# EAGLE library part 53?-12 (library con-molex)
CONNECTOR wire to board 1.25 mm (.049 inch) pitch header
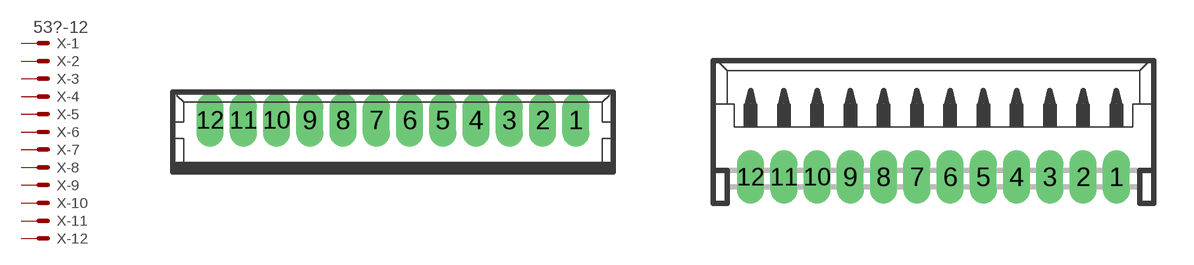
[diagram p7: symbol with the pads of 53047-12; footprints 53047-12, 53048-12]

Designator prefix X; gates -1=MV -2=M -3=M -4=M -5=M -6=M -7=M -8=M -9=M -10=M -11=M -12=M

## 53047-12 (MF: WALDOM/MOLEX; MPN: 53047-1210; OC_FARNELL: 9732896; OC_NEWARK: 18M8169)  [53047-12]
1  -1:S  pas
2  -2:S  pas
3  -3:S  pas
4  -4:S  pas
5  -5:S  pas
6  -6:S  pas
7  -7:S  pas
8  -8:S  pas
9  -9:S  pas
10  -10:S  pas
11  -11:S  pas
12  -12:S  pas

## 53048-12 (MF: WALDOM/MOLEX; MPN: 53048-1210; OC_FARNELL: unknown; OC_NEWARK: 71H4145)  [53048-12]
Pads as for 53047-12

## 53261-12 (MF: MOLEX; MPN: 53261-1271; OC_FARNELL: 1125363; OC_NEWARK: 59J0244)  [53261-12]
Pads as for 53047-12

## 53398-12 (OC_FARNELL: 1125356; OC_NEWARK: unknown)  [53398-12]
Pads as for 53047-12

## Footprint 53047-12 (pad centres in mm)
CONNECTOR wire to board 1.25 mm (.049 inch) pitch header straight Sourcxe: http://www.molex.com/pdm_docs/sd/530470210_sd.pdf
drill 0.5 pad 0.698 long: 1 6.875,0.45; 2 5.625,0.45; 3 4.375,0.45; 4 3.125,0.45; 5 1.875,0.45; 6 0.625,0.45; 7 -0.625,0.45; 8 -1.875,0.45; 9 -3.125,0.45; 10 -4.375,0.45; 11 -5.625,0.45; 12 -6.875,0.45

## Footprint 53048-12 (pad centres in mm)
CONNECTOR wire to board 1.25 mm (.049 inch) pitch header right angle
drill 0.5 pad 0.698 long: 1 6.875,-1.25; 2 5.625,-1.25; 3 4.375,-1.25; 4 3.125,-1.25; 5 1.875,-1.25; 6 0.625,-1.25; 7 -0.625,-1.25; 8 -1.875,-1.25; 9 -3.125,-1.25; 10 -4.375,-1.25; 11 -5.625,-1.25; 12 -6.875,-1.25

## Footprint 53261-12 (pad centres in mm)
CONNECTOR wire to board 1.25 mm (.049 inch) pitch header SMT right angle
smd 0.8 x 2: 1 6.875,-2.5; 2 5.625,-2.5; 3 4.375,-2.5; 4 3.125,-2.5; 5 1.875,-2.5; 6 0.625,-2.5; 7 -0.625,-2.5; 8 -1.875,-2.5; 9 -3.125,-2.5; 10 -4.375,-2.5; 11 -5.625,-2.5; 12 -6.875,-2.5
smd 2.1 x 3: S1 9.375,0.625; S2 -9.375,0.625

## Footprint 53398-12 (pad centres in mm)
CONNECTOR wire to board 1.25 mm (.049 inch) pitch header SMT straight
smd 0.8 x 1.8: 1 6.875,-2.5; 2 5.625,-2.5; 3 4.375,-2.5; 4 3.125,-2.5; 5 1.875,-2.5; 6 0.625,-2.5; 7 -0.625,-2.5; 8 -1.875,-2.5; 9 -3.125,-2.5; 10 -4.375,-2.5; 11 -5.625,-2.5; 12 -6.875,-2.5
smd 2.1 x 3: S1 9.375,0.625; S2 -9.375,0.625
